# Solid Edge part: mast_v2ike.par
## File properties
Author: kaisa
Template: iso metric part.par
Last saved by: kaisa
Revision: 2
Application: Solid Edge
Accuracy: 0.990
Username: kaisa
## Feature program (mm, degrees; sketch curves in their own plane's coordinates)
sketch for "unnamed RevolvedProtrusion 1" plane through (0, 0, 0) normal (1, 0, 0) x-axis (0, 1, 0)
  line (0, 0) -> (0, 200)
  line (0, 200) -> (3, 200)
  line (3, 200) -> (3, 0)
  line (3, 0) -> (0, 0)
revolve "unnamed RevolvedProtrusion 1" add finite 360 deg
sketch for "unnamed RevolvedProtrusion 2" plane through (-5, 0, 0) normal (1, 0, 0) x-axis (0, 1, 0)
  line (-75, 127.8222) -> (75, 127.8222)
  line (75, 126.4829) -> (75, 127.8222)
  line (-75, 126.4829) -> (75, 126.4829)
  line (-75, 127.8222) -> (-75, 126.4829)
revolve "unnamed RevolvedProtrusion 2" add finite 360 deg
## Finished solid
Body 1: solid body, 6 faces, 4 edges, 0 vertices, 2 separate solids.
  Faces by surface: plane 4, cylinder 2
  Edges by curve: circle 4
Bounding box of the edges (mm): 9.339 x 150.000 x 200.000, from (-6.3393, -75, 0) to (3, 75, 200).
Cylindrical faces by radius (mm): R1.3393 x1, R3 x1
Planar faces by outward normal: +y 1, +z 1, -y 1, -z 1
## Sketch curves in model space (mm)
line (-5, 75, 126.4829) -> (-5, 75, 127.8222)
line (-5, -75, 126.4829) -> (-5, 75, 126.4829)
line (-5, -75, 127.8222) -> (-5, -75, 126.4829)
line (-5, -75, 127.8222) -> (-5, 75, 127.8222)
line (0, 0, 200) -> (0, 3, 200)
line (0, 3, 200) -> (0, 3, 0)
line (0, 3, 0) -> (0, 0, 0)
line (0, 0, 0) -> (0, 0, 200)
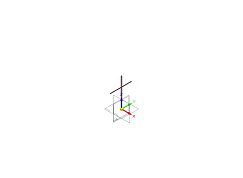
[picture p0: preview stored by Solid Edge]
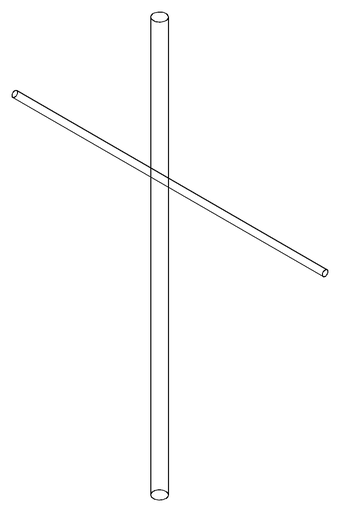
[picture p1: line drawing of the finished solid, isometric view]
